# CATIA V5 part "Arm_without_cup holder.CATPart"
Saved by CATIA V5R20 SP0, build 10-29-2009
Part number: Part1
Material "Plastic": density 1200 kg/m3, Young's modulus 2.2e+09 Pa, Poisson ratio 0.38, thermal expansion 6.84e-05 1/K
Bounding box of the stored display mesh (mm): x -46.402 to 0, y -40 to 15, z -29.997 to 82.5
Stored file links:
  C:\Users\user\SkyDrive\Stuff\cad\Instructables\Hand adapter\CATIA V5, STEP ,IGES Files\Arm_without_cup holder.CATPart
  C:\Program Files\Dassault Systemes\B20\win_b64\reffiles\standard\MetricThinPitch.txt
  C:\Program Files\Dassault Systemes\B20\win_b64\startup\materials\Catalog.CATMaterial
  C:\Program Files\Dassault Systemes\B20\win_b64\reffiles\standard\MetricThickPitch.txt
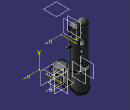
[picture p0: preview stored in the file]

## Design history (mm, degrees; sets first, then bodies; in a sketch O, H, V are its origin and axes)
Body1 (main body), material "Plastic"
  Sketch1 on xy-plane, origin (0, 0, 0), H (1, 0, 0), V (0, 1, 0)
    circle A1 centre (-31.4018, 0) radius 15
    radius A1 = 15
  Pad1: profile Sketch1, direction (0, 0, 1), length 10
  Sketch2 on end face of Pad1, origin (0, 0, 10), H (1, 0, 0), V (0, 1, 0)
    circle A1 centre (-23.9018, 0) radius 7.5
    point P1 (-23.9018, 0)
    circle A2 centre (-38.9018, 0) radius 7.5
    point P2 (-38.9018, 0)
    point P3 (-31.4018, 0)
    reference projected circle E1 centre (-31.4018, 0) radius 15 from edge [face of Pad1 from Sketch1.A1 | end face of Pad1]
    radius A1 = 7.5
    radius A2 = 7.5
    coincidence: P1 H, P2 H, P3 H
    tangency: A2 A1
    concentricity: P3 E1
    equidistance: P2 P1 P3
  Pad2: profile Sketch2, direction (0, 0, 1), length 65
  Plane1: type Offset, RefPlane zx-plane, Offset -7.5
  Sketch3 on Plane1, origin (0, -7.5, 0), H (-1, 0, 0), V (0, 0, 1)
    reference projected line E1 (16.4018, 10) -> (31.4018, 10) from edge [end face of Pad1 | face of Pad2 from Sketch2.A1]
    construction line L1 (31.4018, 75) -> (31.4018, 21.2562)
    spline S1 through (31.4018, 42.5) (36.4018, 50) (31.4018, 57.5) (26.4018, 50) (31.4018, 42.5)
    construction line L2 (93.6923, 50) -> (-93.4071, 50)
    construction line L3 (100.8473, 35) -> (-86.2521, 35)
    spline S2 through (31.4018, 31) (34.9018, 35) (31.4018, 39) (27.9018, 35) (31.4018, 31)
    line L4 (33.9018, 25) -> (28.9018, 25)
    line L5 (28.9018, 25) -> (28.9018, 15)
    line L6 (28.9018, 15) -> (33.9018, 15)
    line L7 (33.9018, 15) -> (33.9018, 25)
    construction line L8 (109.543, 20) -> (-92.7825, 20)
    point P16 (31.4018, 65)
    point P17 (31.4018, 60.9585)
    point P18 (34.9018, 62.9793)
    point P19 (34.9018, 67.0207)
    point P20 (31.4018, 69.0415)
    point P21 (27.9018, 67.0207)
    point P22 (27.9018, 62.9793)
    point P23 (33.1518, 61.9689)
    line L9 (31.4018, 60.9585) -> (34.9018, 62.9793)
    line L10 (34.9018, 62.9793) -> (34.9018, 67.0207)
    line L11 (34.9018, 67.0207) -> (31.4018, 69.0415)
    line L12 (31.4018, 69.0415) -> (27.9018, 67.0207)
    line L13 (27.9018, 67.0207) -> (27.9018, 62.9793)
    line L14 (27.9018, 62.9793) -> (31.4018, 60.9585)
    construction line L15 (31.4018, 65) -> (33.1518, 61.9689)
    construction circle A1 centre (31.4018, 65) radius 4.0415
    construction arc A2 centre (27.9018, 67.0207) radius 4.0415 from (31.4018, 69.0415) to (27.9018, 62.9793) cw
    construction arc A3 centre (34.9018, 62.9793) radius 4.0415 from (34.9018, 67.0207) to (31.4018, 60.9585) ccw
    point P24 (31.4018, 42.5)
    point P25 (31.4018, 57.5)
    point P26 (31.4018, 42.5)
    point P27 (36.4018, 50)
    point P28 (26.4018, 50)
    point P29 (34.9018, 35)
    point P30 (27.9018, 35)
    point P31 (31.4018, 39)
    point P32 (31.4018, 31)
    point P33 (31.4018, 31)
    distance P27 P28 = 10
    distance P25 P26 = 15
    distance P29 P30 = 7
    distance P31 P32 = 8
    length L4 = 5
    distance L4 L6 = 10
    distance L8 E1 = 10
    distance L3 L8 = 15
    distance L2 L3 = 15
    length L15 = 3.5
    distance P16 L2 = 15
    vertical: L1 V, L5 V, L7 V
    coincidence: P24 L1, P25 L1, P26 P24, P27 L2, P28 L2, P29 L3, P30 L3, P32 P33, P32 L1, P16 L1, A1 P17, A1 P18, A1 P19, A1 P20, A1 P21, A1 P22, A2 P16, A3 P16, P20 L1
    symmetry: P27 P28 L1, P25 P26 L2, P31 P32 L3, P29 P30 L1, L7 L5 L1, L4 L6 L8
    horizontal: L2 H, L4 H, L6 H, L8 H
    midpoint: P23 L9
    parallelism: L9 L12
  Pocket1: profile Sketch3, direction (0, 1, 0), through (limit type 3)
  Plane2: type Offset, RefPlane zx-plane, Offset -25
  Sketch4 on end face of Pad2, origin (0, 0, 75), H (1, 0, 0), V (0, 1, 0)
    point P1 (-23.9018, 0)
    reference projected circle E1 centre (-23.9018, 0) radius 7.5 from edge [face of Pad2 from Sketch2.A1 | end face of Pad2]
    concentricity: E1 P1
  Sketch5 on start face of Pad1, origin (0, 0, 0), H (1, 0, 0), V (0, -1, 0)
    circle A1 centre (-31.4018, 0) radius 15
    reference projected circle E1 centre (-31.4018, 0) radius 15 from edge [start face of Pad1 | face of Pad1 from Sketch1.A1]
    radius A1 = 15
    concentricity: A1 E1
  Sketch6 on start face of Pad1, origin (0, 0, 0), H (1, 0, 0), V (0, -1, 0)
    point P1 (-31.4018, 0)
    reference projected circle E1 centre (-31.4018, 0) radius 15 from edge [start face of Pad1 | face of Pad1 from Sketch1.A1]
    coincidence: P1 H
    concentricity: P1 E1
  Plane3: type OffsetPt, RefPlane yz-plane, RefPoint Sketch6
  Sketch7 on Plane3, origin (-31.4018, 0, 0), H (0, 1, 0), V (0, 0, 1)
    line L1 (0, 0) -> (0, -15)
    reference projected point E1 (0, 0) from Sketch6
    line L2 (0, -15) -> (-40, -15)
    length L1 = 15
    length L2 = 40
    vertical: L1 V
    coincidence: E1 L1
    horizontal: L2 H
  Rib1: profile Sketch5, centre curve Sketch7
  Plane4: type OffsetPt, RefPlane yz-plane, RefPoint Sketch4
  Sketch8 on end face of Pad2, origin (0, 0, 75), H (1, 0, 0), V (0, 1, 0)
    line L1 (-46.4018, 0) -> (-31.4018, 0)
    arc A1 centre (-38.9018, 0) radius 7.5 from (-31.4018, 0) to (-46.4018, 0) ccw
    point P1 (-38.9018, 0)
    reference projected circle E1 centre (-38.9018, 0) radius 7.5 from edge [face of Pad2 from Sketch2.A2 | end face of Pad2]
    radius A1 = 7.5
    horizontal: L1 H
    coincidence: P1 L1
    concentricity: A1 E1
  Shaft1: profile Sketch8, axis Sketch8.L1, angle 180
  Sketch9 on face of Rib1, origin (0, -40, 0), H (1, 0, 0), V (0, 0, 1)
    point P1 (-31.4018, -15)
    reference projected circle E1 centre (-31.4018, -15) radius 15 from edge [face of Rib1 | face of Rib1]
    concentricity: P1 E1
  Plane5: type OffsetPt, RefPlane xy-plane, RefPoint Sketch9
  Plane6: type Offset, RefPlane Plane3, Offset -15
  Plane7: type Offset, RefPlane Plane4, Offset 7.5
  Sketch10 on Plane7, origin (-16.4018, 0, 0), H (0, 1, 0), V (0, 0, 1)
    line L1 (-63.5987, 125.8143) -> (-13.5987, 125.8143)
    line L2 (-13.5987, 125.8143) -> (-13.5987, 120.8143)
    line L3 (-13.5987, 120.8143) -> (-63.5987, 120.8143)
    line L4 (-63.5987, 120.8143) -> (-63.5987, 125.8143)
    length L1 = 50
    length L2 = 5
    horizontal: L1 H, L3 H
    vertical: L2 V, L4 V
  Pocket2: profile Sketch10, direction (-1, 0, 0), length 8
  Fillet1: radius 6, on edge [face of Rib1 | face of Rib1]
  Sketch11 on Plane6, origin (-46.4018, 0, 0), H (0, 1, 0), V (0, 0, 1)
    line L1 (-15, -2.5) -> (-40, -2.5)
    line L2 (-40, -2.5) -> (-40, -27.5)
    line L3 (-40, -27.5) -> (-15, -27.5)
    line L4 (-15, -27.5) -> (-15, -2.5)
    point P2 (-40, -2.5)
    point P3 (-40, -27.5)
    reference projected point E1 (-40, -15) from Sketch9.P1
    length L2 = 25
    length L3 = 25
    horizontal: L1 H, L3 H
    vertical: L2 V, L4 V
    equidistance: P3 P2 E1
    coincidence: L2 E1
  Pocket3: profile Sketch11, direction (1, 0, 0), length 5
  Sketch12 on Plane7, origin (-16.4018, 0, 0), H (0, 1, 0), V (0, 0, 1)
    reference projected point E1 (-40, -15) from Sketch9.P1
    line L1 (-40, -2.5) -> (-15, -2.5)
    line L2 (-15, -2.5) -> (-15, -27.5)
    line L3 (-15, -27.5) -> (-40, -27.5)
    line L4 (-40, -27.5) -> (-40, -2.5)
    length L2 = 25
    length L1 = 25
    horizontal: L1 H, L3 H
    vertical: L2 V, L4 V
    midpoint: E1 L4
    coincidence: E1 L4
  Pocket4: profile Sketch12, direction (-1, 0, 0), length 5
  Sketch13 on end face of Pocket3, origin (-41.4018, -22.9671, -18.1896), H (0, 1, 0), V (0, 0, -1)
    point P1 (-4.5329, -3.1896)
    reference projected line E1 (-17.0329, -14.37) -> (-17.0329, 7.9907) from edge [end face of Pocket3 | face of Rib1]
    reference projected line E2 (7.9671, -13.9039) -> (7.9671, 7.9907) from edge [face of Rib1 | face of Pocket3 from Sketch11.L4]
    reference projected line E3 (-17.0329, 7.9907) -> (7.9671, 7.9907) from edge [end face of Pocket3 | face of Rib1]
    reference projected line E4 (-17.0329, -14.37) -> (7.3147, -14.37) from edge [face of Rib1 | end face of Pocket3]
    equidistance: E1 E2 P1, E3 E4 P1
  Hole1: placed by Sketch13, at (-41.4018, -27.5, -15) direction (1, 0, 0), diameter 8, through (limit type 3)
  Sketch14 on Plane7, origin (-16.4018, 0, 0), H (0, 1, 0), V (0, 0, 1)
    circle A1 centre (0, 50) radius 2.5
    point P1 (0, 50)
    construction line L1 (0, 95.8845) -> (0, 52.9037)
    point P2 (0, 95.8845)
    reference projected point E1 (0, 75) from Sketch4
    radius A1 = 2.5
    distance E1 P1 = 25
    coincidence: P2 V, P1 L1
    vertical: L1 V
  Pad3: profile Sketch14, direction (1, 0, 0), length 5, mirrored extent
  Sketch15 on end face of Pad3, origin (-11.4018, 0, 0), H (0, 1, 0), V (0, 0, 1)
    projected circle E1 centre (0, 50) radius 2.5 from edge [face of Pad3 from Sketch14.A1 | end face of Pad3]
    projected arc E2 centre (0, 50) radius 2.5 from (0, 52.5) to (0, 47.5) ccw from edge [face of Pad3 from Sketch14.A1 | end face of Pad3]
    line L1 (0, 52.5) -> (0, 47.5)
    point P1 (0, 47.5)
    point P2 (0, 52.5)
    point P3 (0, 52.5)
    point P4 (0, 47.5)
    vertical: L1 V
    coincidence: L1 P1, L1 P2, E1 P3, E1 P4, P1 P4, P2 P3
  Shaft2: profile Sketch15, axis Sketch15.L1, angle 180
  Fillet2: radius 3, on edge [face of Rib1 | face of Rib1]
  Fillet3: radius 3, on edge [face of Rib1 | face of Rib1]
  Sketch16 on Plane7, origin (-16.4018, 0, 0), H (0, 1, 0), V (0, 0, 1)
    arc A1 centre (0, 65) radius 3 from (2.958, 65.5) to (-2.958, 65.5) ccw
    point P1 (0, 65)
    line L1 (-4, 65.5) -> (-2.958, 65.5)
    line L2 (4, 65.5) -> (4, 64.5)
    line L3 (4, 64.5) -> (2.958, 64.5)
    line L4 (-4, 64.5) -> (-4, 65.5)
    point P4 (4, 64.5)
    point P5 (-4, 64.5)
    reference projected line E1 (-15, 10) -> (15, 10) from edge [face of Rib1 | end face of Pad1]
    point P9 (2.958, 65.5)
    arc A2 centre (0, 65) radius 3 from (-2.958, 64.5) to (2.958, 64.5) ccw
    point P11 (-2.958, 64.5)
    line L5 (-2.958, 64.5) -> (-4, 64.5)
    line L6 (2.958, 65.5) -> (4, 65.5)
    radius A1 = 3
    length L2 = 1
    distance E1 P1 = 55
    distance P4 P5 = 8
    coincidence: P1 V, L1 P9, L3 P11, A1 A2, L3 L5, L1 L6
    horizontal: L1 H, L3 H, L5 H, L6 H
    vertical: L2 V, L4 V
    equidistance: L4 L2 P1, L1 L3 P1
  Pocket5: profile Sketch16, direction (-1, 0, 0), length 10
  Plane8: type Offset, RefPlane Plane5, Offset 94
  Sketch17 on Plane8, origin (0, 0, 79), H (1, 0, 0), V (0, 1, 0)
    line L1 (-31.6518, 1) -> (-31.1518, 1)
    line L2 (-31.1518, 1) -> (-31.1518, -1)
    line L3 (-31.1518, -1) -> (-31.6518, -1)
    line L4 (-31.6518, -1) -> (-31.6518, 1)
    reference projected point E1 (-31.4018, 0) from Sketch6
    reference projected point E2 (-31.4018, 0) from Sketch6
    length L1 = 0.5
    length L2 = 2
    horizontal: L1 H, L3 H
    vertical: L2 V, L4 V
    equidistance: L4 L2 E1, L1 L3 E2
  Pocket6: profile Sketch17, direction (0, 0, -1), length 69
  Sketch18 on end face of Pad2, origin (0, 0, 75), H (1, 0, 0), V (0, 1, 0)
    arc A1 centre (-23.9018, 0) radius 7.5 from (-24.4521, 7.4798) to (-23.3515, -7.4798) ccw
    point P1 (-23.9018, 0)
    reference projected circle E1 centre (-23.9018, 0) radius 7.5 from edge [face of Pad2 from Sketch2.A1 | end face of Pad2]
    line L1 (-24.4521, 7.4798) -> (-23.3515, -7.4798)
    radius A1 = 7.5
    coincidence: P1 H, P1 L1
    concentricity: A1 E1
  Shaft3: profile Sketch18, axis Sketch18.L1, angle 180
  Sketch19 on Plane7, origin (-16.4018, 0, 0), H (0, 1, 0), V (0, 0, 1)
    point P1 (0, 75)
    point P2 (4, 75)
    point P3 (2, 78.4641)
    point P4 (-2, 78.4641)
    point P5 (-4, 75)
    point P6 (-2, 71.5359)
    point P7 (2, 71.5359)
    point P8 (3, 76.7321)
    line L1 (4, 75) -> (2, 78.4641)
    line L2 (2, 78.4641) -> (-2, 78.4641)
    line L3 (-2, 78.4641) -> (-4, 75)
    line L4 (-4, 75) -> (-2, 71.5359)
    line L5 (-2, 71.5359) -> (2, 71.5359)
    line L6 (2, 71.5359) -> (4, 75)
    construction line L7 (0, 75) -> (3, 76.7321)
    construction circle A1 centre (0, 75) radius 4
    construction arc A2 centre (-2, 71.5359) radius 4 from (-4, 75) to (2, 71.5359) cw
    construction arc A3 centre (2, 78.4641) radius 4 from (-2, 78.4641) to (4, 75) ccw
    reference projected line E1 (-15, 10) -> (15, 10) from edge [face of Rib1 | end face of Pad1]
    point P9 (-15, 10)
    point P10 (15, 10)
    radius A2 = 4
    distance P1 E1 = 65
    coincidence: P1 V, A1 P2, A1 P3, A1 P4, A1 P5, A1 P6, A1 P7, A2 P1, A3 P1
    midpoint: P8 L1
    parallelism: L1 L4, L5 E1
    equidistance: P10 P9 P1
  Pocket7: profile Sketch19, direction (-1, 0, 0), length 10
